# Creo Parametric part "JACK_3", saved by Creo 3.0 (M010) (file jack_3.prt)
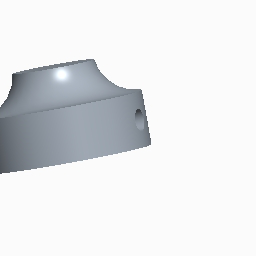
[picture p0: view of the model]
Units: millimeter Newton Second (mmNs); MM, TONNE, SECS

Created from: MMNS_PART_SOLID.PRT

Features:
  1. datum plane "RIGHT"
  2. datum plane "TOP"
  3. datum plane "FRONT"
  4. coordinate system
  5. protrusion
  6. datum plane "DTM1"
  7. hole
